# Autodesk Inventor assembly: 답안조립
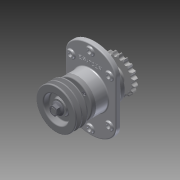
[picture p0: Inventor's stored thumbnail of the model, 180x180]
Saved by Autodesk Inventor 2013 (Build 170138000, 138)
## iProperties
Created: 2015-02
Part Number: 답안조립
Document SubType Name: Assembly
Designer: Administrator
Author: Administrator
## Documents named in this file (12)
- C:\Users\Administrator\Desktop\450208V1002\답안조립.iam
- C:\Users\Administrator\Desktop\450208V1002\본체.ipt
- C:\Users\Administrator\Desktop\450208V1002\2-커버.ipt
- C:\Users\Administrator\Desktop\450208V1002\3-축.ipt
- C:\Users\Administrator\Desktop\450208V1002\4-V벨트풀리.ipt
- C:\Users\Administrator\Desktop\450208V1002\5-체인 스프로킷.ipt
- C:\Users\Administrator\Desktop\450208V1002\6-베어링 6206.ipt
- C:\Users\Administrator\Desktop\450208V1002\7-부시.ipt
- C:\Users\Administrator\Desktop\450208V1002\8-오일실 30x42.ipt
- C:\Users\Administrator\Desktop\450208V1002\9-M16-너트.ipt
- C:\Users\Administrator\Desktop\450208V1002\10-M6.ipt
- C:\Users\Administrator\Desktop\450208V1002\11-키 6x6.ipt
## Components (22 placed, 10 different names)
1. 2-커버:1
2. 3-축:1 — 각도:1, 각도:2
3. 4-V벨트풀리:1 — 각도:3
4. 5-체인 스프로킷:1 — 각도:4
5. 6-베어링 6206:1
6. 7-부시:1
7. 8-8-오일실 30x42:1
8. 9-M16 너트:1
9. 11-키 6x6:1 — 각도:1, 각도:3
10. 11-키 6x6:2 — 각도:2, 각도:4
11. 2-커버:2
12. 6-베어링 6206:2
13. 8-8-오일실 30x42:2
14. 9-M16 너트:2
15. 10-M6:2
16. 10-M6:1
17. 10-M6:3
18. 10-M6:4
19. 10-M6:5
20. 10-M6:6
21. 10-M6:7
22. 10-M6:8
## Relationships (4: Angle 4)
- 각도:1 [Angle]: 3-축:1 ↔ 11-키 6x6:1
- 각도:2 [Angle]: 3-축:1 ↔ 11-키 6x6:2
- 각도:3 [Angle]: 4-V벨트풀리:1 ↔ 11-키 6x6:1
- 각도:4 [Angle]: 5-체인 스프로킷:1 ↔ 11-키 6x6:2
